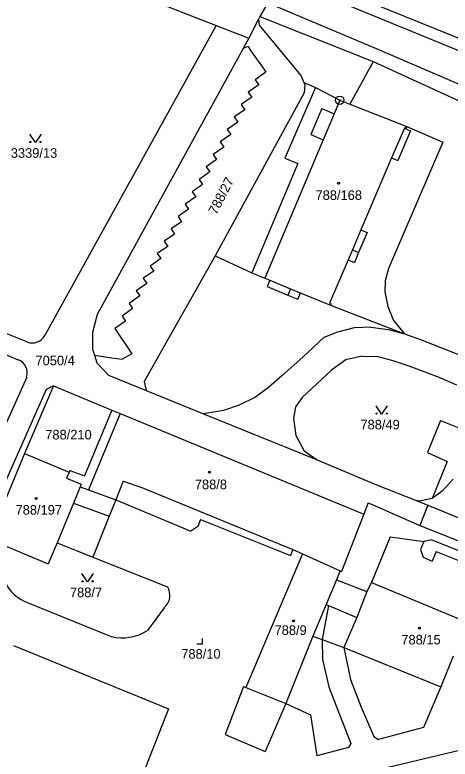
# Model space of a CAD drawing. Extents: x -593183 to -588034, y -1130415 to -1124994.
# Drawn here: x -592010.8 to -591933.7, y -1128398.9 to -1128267.2 of the extents above; entities that cross this region are included whole.
import ezdxf

# ---------------------------------------------------------------- set-up
doc = ezdxf.new("R2010")
doc.units = 0
for name, color, linetype in [('Vrstva 1', 7, 'Continuous'), ('Vrstva 18', 7, 'Continuous'), ('Vrstva 19', 7, 'Continuous'), ('Vrstva 24', 7, 'Continuous'), ('Vrstva 25', 7, 'Continuous'), ('Vrstva 4', 7, 'Continuous')]:
    doc.layers.add(name, color=color, linetype=linetype)

msp = doc.modelspace()

# ---------------------------------------------------------------- linework, layer by layer
at = {"layer": 'Vrstva 1'}
for p, q in [((-592007.9, -1128256.18), (-591975.11, -1128269.03)), ((-591960.97, -1128261.67), (-591931.65, -1128273.68)), ((-591955.86, -1128261.68), (-591814.3, -1128319.36)), ((-591965.98, -1128265.01), (-591967.38, -1128267.44)), ((-591965.98, -1128265.01), (-591946.82, -1128273.12)), ((-591967.63, -1128267.93), (-591969.35, -1128271.29)), ((-591967.38, -1128267.44), (-591967.63, -1128267.93)), ((-591967.38, -1128267.44), (-591947.92, -1128275.17)), ((-591975.11, -1128269.03), (-592005.34, -1128323.67)), ((-591975.11, -1128269.03), (-591969.35, -1128271.29)), ((-591969.35, -1128271.29), (-591970.34, -1128273.1)), ((-591970.34, -1128273.1), (-591996.22, -1128320.2)), ((-591946.82, -1128273.12), (-591931.29, -1128279.8)), ((-591947.54, -1128275.75), (-591951.51, -1128282.97)), ((-591947.92, -1128275.17), (-591947.36, -1128275.43)), ((-591947.36, -1128275.43), (-591947.54, -1128275.75)), ((-591947.36, -1128275.43), (-591931.88, -1128282.5)), ((-591959.64, -1128279.15), (-591957.58, -1128280.03)), ((-591959.64, -1128279.15), (-591959.45, -1128279.63)), ((-591959.45, -1128279.63), (-591959.58, -1128280.96)), ((-591957.58, -1128280.03), (-591953.27, -1128282.28)), ((-591959.58, -1128280.96), (-591975.29, -1128309.8)), ((-591953.27, -1128282.28), (-591951.51, -1128282.97)), ((-591951.51, -1128282.97), (-591941.4, -1128286.95)), ((-591941.4, -1128286.95), (-591935.02, -1128289.71)), ((-591935.02, -1128289.71), (-591944.66, -1128312.09)), ((-591975.29, -1128309.8), (-591968.82, -1128312.83)), ((-591968.82, -1128312.83), (-591966.52, -1128313.8)), ((-591944.66, -1128312.09), (-591945.21, -1128314.24)), ((-592036.9, -1128313.48), (-592008.84, -1128324.96)), ((-591966.52, -1128313.8), (-591965.64, -1128314.16)), ((-591965.64, -1128314.16), (-591966.1, -1128315.28)), ((-591945.21, -1128314.24), (-591945.29, -1128316.22)), ((-591966.1, -1128315.28), (-591962.43, -1128316.79)), ((-591962.43, -1128316.79), (-591960.71, -1128317.49)), ((-591960.26, -1128316.38), (-591960.71, -1128317.49)), ((-591960.26, -1128316.38), (-591954.92, -1128318.58)), ((-591945.29, -1128316.22), (-591944.75, -1128318.8)), ((-592031.02, -1128319.7), (-592010.18, -1128328.23)), ((-591954.92, -1128318.58), (-591941.8, -1128323.63)), ((-591944.75, -1128318.8), (-591943.78, -1128321.25)), ((-591996.22, -1128320.2), (-591997, -1128323.38)), ((-591947.77, -1128322.44), (-591950.73, -1128322.57)), ((-591947.77, -1128322.44), (-591944.62, -1128322.89)), ((-591943.78, -1128321.25), (-591941.8, -1128323.63)), ((-591997, -1128323.38), (-591997.01, -1128326.38)), ((-591953.68, -1128323.36), (-591956.07, -1128324.28)), ((-591950.73, -1128322.57), (-591953.68, -1128323.36)), ((-591944.62, -1128322.89), (-591941.8, -1128323.63)), ((-591941.8, -1128323.63), (-591938.97, -1128324.65)), ((-591956.07, -1128324.28), (-591959.73, -1128327.7)), ((-591938.97, -1128324.65), (-591927.04, -1128329.4)), ((-591997.01, -1128326.38), (-591996.69, -1128327.42)), ((-591996.69, -1128327.42), (-591996.27, -1128328.78)), ((-591959.73, -1128327.7), (-591963.53, -1128331.07)), ((-591949.27, -1128327.62), (-591952.17, -1128328.24)), ((-591949.27, -1128327.62), (-591946.54, -1128327.67)), ((-591946.54, -1128327.67), (-591943.88, -1128328.34)), ((-591996.27, -1128328.78), (-591994.2, -1128330.95)), ((-591952.17, -1128328.24), (-591954.7, -1128330.07)), ((-591943.88, -1128328.34), (-591941.05, -1128329.33)), ((-591954.7, -1128330.07), (-591959.92, -1128334.92)), ((-591941.05, -1128329.33), (-591938.19, -1128330.39)), ((-591938.19, -1128330.39), (-591935.41, -1128331.44)), ((-592008.67, -1128331.34), (-592017.33, -1128350.6)), ((-591994.2, -1128330.95), (-591987.53, -1128333.69)), ((-591963.53, -1128331.07), (-591965.89, -1128333.13)), ((-591935.41, -1128331.44), (-591932.59, -1128332.65)), ((-592003.92, -1128332.84), (-592009.05, -1128344.85)), ((-592003.92, -1128332.84), (-591993.62, -1128337.17)), ((-591987.53, -1128333.69), (-591977.4, -1128337.79)), ((-591965.89, -1128333.13), (-591968.2, -1128334.84)), ((-591968.2, -1128334.84), (-591971.05, -1128336.27)), ((-591959.92, -1128334.92), (-591961.07, -1128336.55)), ((-591971.05, -1128336.27), (-591973.81, -1128337.2)), ((-591961.07, -1128336.55), (-591961.43, -1128338.62)), ((-591993.62, -1128337.17), (-591998.41, -1128348.78)), ((-591993.62, -1128337.17), (-591992.12, -1128337.75)), ((-591992.12, -1128337.75), (-591949, -1128355.55)), ((-591973.81, -1128337.2), (-591977.4, -1128337.79)), ((-591977.4, -1128337.79), (-591957.29, -1128345.98)), ((-591961.43, -1128338.62), (-591961.04, -1128341.65)), ((-591961.04, -1128341.65), (-591959.55, -1128344.36)), ((-592009.05, -1128344.85), (-592013.81, -1128356.28)), ((-592009.05, -1128344.85), (-592001.18, -1128348.13)), ((-591959.55, -1128344.36), (-591957.29, -1128345.98)), ((-591957.29, -1128345.98), (-591946.79, -1128350.38)), ((-592001.18, -1128348.13), (-592001.62, -1128349.19)), ((-592001.02, -1128347.83), (-592001.18, -1128348.13)), ((-592001.02, -1128347.83), (-591998.41, -1128348.78)), ((-592001.62, -1128349.19), (-591999.03, -1128350.27)), ((-591933.18, -1128349.35), (-591935.12, -1128351.5)), ((-591999.2, -1128350.73), (-592000.38, -1128353.6)), ((-591999.03, -1128350.27), (-591999.2, -1128350.73)), ((-591946.79, -1128350.38), (-591939.87, -1128353.08)), ((-591935.12, -1128351.5), (-591936.93, -1128352.77)), ((-591936.93, -1128352.77), (-591938.85, -1128353.23)), ((-592000.38, -1128353.6), (-592003.29, -1128360.66)), ((-591992.91, -1128353.01), (-591994.09, -1128355.94)), ((-591992.91, -1128353.01), (-591979.64, -1128358.61)), ((-591948.22, -1128353.54), (-591949, -1128355.55)), ((-591948.22, -1128353.54), (-591947.55, -1128353.84)), ((-591947.55, -1128353.84), (-591939.08, -1128357.55)), ((-591939.87, -1128353.08), (-591937.65, -1128353.99)), ((-591939.87, -1128353.08), (-591938.85, -1128353.23)), ((-591937.65, -1128353.99), (-591939.08, -1128357.55)), ((-591937.65, -1128353.99), (-591900.44, -1128369.15)), ((-591994.09, -1128355.94), (-591996.96, -1128363.21)), ((-591977.89, -1128356.49), (-591978.4, -1128357.75)), ((-591977.89, -1128356.49), (-591962, -1128362.91)), ((-591949, -1128355.55), (-591952.93, -1128365.72)), ((-591978.4, -1128357.75), (-591979.64, -1128358.61)), ((-591939.08, -1128357.55), (-591915.81, -1128366.85)), ((-592003.29, -1128360.66), (-592004.84, -1128364.38)), ((-592003.29, -1128360.66), (-591996.96, -1128363.21)), ((-591944.35, -1128359.61), (-591947.64, -1128367.69)), ((-591944.35, -1128359.61), (-591938.4, -1128360.4)), ((-591938.4, -1128360.4), (-591938.98, -1128361.8)), ((-592012.2, -1128361.31), (-592004.84, -1128364.38)), ((-591961.57, -1128361.84), (-591962, -1128362.91)), ((-591961.57, -1128361.84), (-591959.84, -1128362.59)), ((-591938.98, -1128361.8), (-591938.53, -1128363.17)), ((-591996.96, -1128363.21), (-591983.73, -1128368.41)), ((-591959.84, -1128362.59), (-591969.88, -1128386.26)), ((-591959.84, -1128362.59), (-591953.21, -1128365.61)), ((-591938.53, -1128363.17), (-591936.89, -1128363.91)), ((-591936.21, -1128362.18), (-591936.89, -1128363.91)), ((-591936.21, -1128362.18), (-591917.66, -1128369.72)), ((-591953.21, -1128365.61), (-591953.86, -1128367.18)), ((-591953.21, -1128365.61), (-591952.93, -1128365.72)), ((-591953.86, -1128367.18), (-591955.67, -1128371.55)), ((-591953.86, -1128367.18), (-591948.49, -1128369.28)), ((-591947.64, -1128367.69), (-591948.49, -1128369.28)), ((-591947.64, -1128367.69), (-591900.03, -1128387.39)), ((-592008.99, -1128371.05), (-591993.69, -1128377.24)), ((-591984.33, -1128372.13), (-591987.3, -1128376.19)), ((-591955.67, -1128371.55), (-591958.01, -1128377.18)), ((-591955.67, -1128371.55), (-591955.26, -1128371.72)), ((-591955.26, -1128371.72), (-591950.25, -1128373.87)), ((-591950.25, -1128373.87), (-591952.53, -1128379.19)), ((-591958.01, -1128377.18), (-591962.82, -1128389.12)), ((-592010.99, -1128378.83), (-591983.57, -1128390.02)), ((-591952.53, -1128379.19), (-591935.39, -1128386.13)), ((-591933.2, -1128380.71), (-591935.39, -1128386.13)), ((-591970.3, -1128386.08), (-591973.56, -1128394.57)), ((-591970.3, -1128386.08), (-591969.88, -1128386.26)), ((-591962.82, -1128389.12), (-591966.47, -1128397.6)), ((-591983.57, -1128390.02), (-591993.46, -1128415.16)), ((-591973.56, -1128394.57), (-591966.47, -1128397.6)), ((-591929.86, -1128396.89), (-591949.87, -1128401.69))]:
    msp.add_line(p, q, dxfattribs=at)
for centre, radius, start, end in [((-592007.68, -1128322.7), 2.54, 242.9083, 337.5565), ((-592011.03, -1128330.56), 2.48, 341.7929, 70.0031), ((-592006.19, -1128364.65), 6.98, 196.4569, 246.3905), ((-591986.24, -1128369.91), 2.92, 310.7064, 30.9689), ((-591991.73, -1128369.18), 8.29, 256.3453, 302.3175)]:
    msp.add_arc(centre, radius, start, end, dxfattribs=at)
at = {"layer": 'Vrstva 24'}
for radius in [0.75, 0.0903]:
    msp.add_circle((-591953.27, -1128282.28), radius, dxfattribs=at)
at = {"layer": 'Vrstva 25'}
for q in [(-591977.57, -1128377.61), (-591978.57, -1128378.61)]:
    msp.add_line((-591977.57, -1128378.61), q, dxfattribs=at)
for points in [[(-592006.13, -1128288.27), (-592007.13, -1128289.77), (-592008.13, -1128288.27)], [(-591944.85, -1128336.36), (-591945.85, -1128337.86), (-591946.85, -1128336.36)], [(-591996.9, -1128366.07), (-591997.9, -1128367.57), (-591998.9, -1128366.07)]]:
    msp.add_lwpolyline(points, dxfattribs=at)
for centre, radius in [((-592008.03, -1128289.67), 0.1), ((-592006.23, -1128289.67), 0.1), ((-591953.46, -1128296.96), 0.175), ((-591953.46, -1128296.96), 0.15), ((-591946.75, -1128337.76), 0.1), ((-591944.95, -1128337.76), 0.1), ((-591976.31, -1128348.13), 0.175), ((-591976.31, -1128348.13), 0.15), ((-592007, -1128352.81), 0.175), ((-592007, -1128352.81), 0.15), ((-591998.8, -1128367.47), 0.1), ((-591997, -1128367.47), 0.1), ((-591961.47, -1128374.48), 0.175), ((-591961.47, -1128374.48), 0.15), ((-591939.15, -1128375.77), 0.175), ((-591939.15, -1128375.77), 0.15)]:
    msp.add_circle(centre, radius, dxfattribs=at)
at = {"layer": 'Vrstva 4'}
for p, q in [((-591967.63, -1128267.93), (-591967.55, -1128269)), ((-591967.55, -1128269), (-591960.14, -1128277.92)), ((-591969.5, -1128272.78), (-591970.34, -1128273.1)), ((-591969.5, -1128272.78), (-591969.06, -1128273.45)), ((-591969.06, -1128273.45), (-591966.96, -1128276.42)), ((-591966.33, -1128277.32), (-591968.24, -1128278.69)), ((-591966.96, -1128276.42), (-591966.33, -1128277.32)), ((-591968.24, -1128278.69), (-591967.6, -1128279.58)), ((-591960.14, -1128277.92), (-591959.64, -1128279.15)), ((-591967.6, -1128279.58), (-591969.45, -1128280.83)), ((-591957.58, -1128280.03), (-591962.99, -1128292.51)), ((-591969.45, -1128280.83), (-591968.83, -1128281.74)), ((-591968.83, -1128281.74), (-591970.7, -1128283.06)), ((-591953.27, -1128282.28), (-591954.28, -1128284.68)), ((-591970.07, -1128283.96), (-591971.93, -1128285.24)), ((-591970.7, -1128283.06), (-591970.07, -1128283.96)), ((-591956.44, -1128283.77), (-591958.38, -1128288.37)), ((-591956.44, -1128283.77), (-591954.28, -1128284.68)), ((-591971.93, -1128285.24), (-591971.31, -1128286.15)), ((-591954.28, -1128284.68), (-591956.21, -1128289.28)), ((-591971.31, -1128286.15), (-591973.19, -1128287.47)), ((-591973.19, -1128287.47), (-591972.56, -1128288.37)), ((-591941.82, -1128287.23), (-591944.08, -1128292.5)), ((-591940.72, -1128287.7), (-591942.97, -1128292.97)), ((-591941.77, -1128287.1), (-591941.82, -1128287.23)), ((-591941.82, -1128287.23), (-591940.72, -1128287.7)), ((-591941.77, -1128287.1), (-591941.51, -1128287.21)), ((-591941.4, -1128286.95), (-591941.51, -1128287.21)), ((-591972.56, -1128288.37), (-591974.42, -1128289.65)), ((-591956.21, -1128289.28), (-591966.52, -1128313.8)), ((-591958.38, -1128288.37), (-591956.21, -1128289.28)), ((-591973.8, -1128290.56), (-591975.68, -1128291.88)), ((-591974.42, -1128289.65), (-591973.8, -1128290.56)), ((-591975.68, -1128291.88), (-591975.05, -1128292.78)), ((-591975.05, -1128292.78), (-591976.91, -1128294.07)), ((-591960.69, -1128293.48), (-591968.82, -1128312.83)), ((-591962.99, -1128292.51), (-591960.69, -1128293.48)), ((-591944.08, -1128292.5), (-591949.53, -1128305.24)), ((-591944.08, -1128292.5), (-591942.97, -1128292.97)), ((-591976.91, -1128294.07), (-591976.28, -1128294.97)), ((-591976.28, -1128294.97), (-591978.16, -1128296.29)), ((-591977.53, -1128297.19), (-591979.39, -1128298.48)), ((-591978.16, -1128296.29), (-591977.53, -1128297.19)), ((-591979.39, -1128298.48), (-591978.76, -1128299.38)), ((-591978.76, -1128299.38), (-591980.63, -1128300.66)), ((-591980.63, -1128300.66), (-591980.01, -1128301.57)), ((-591980.01, -1128301.57), (-591981.88, -1128302.89)), ((-591981.25, -1128303.79), (-591983.11, -1128305.07)), ((-591981.88, -1128302.89), (-591981.25, -1128303.79)), ((-591983.11, -1128305.07), (-591982.49, -1128305.98)), ((-591949.53, -1128305.24), (-591951.03, -1128308.76)), ((-591949.53, -1128305.24), (-591948.42, -1128305.72)), ((-591982.49, -1128305.98), (-591984.34, -1128307.26)), ((-591948.42, -1128305.72), (-591949.92, -1128309.23)), ((-591984.34, -1128307.26), (-591983.71, -1128308.16)), ((-591983.71, -1128308.16), (-591985.55, -1128309.4)), ((-591951.03, -1128308.76), (-591951.78, -1128310.52)), ((-591951.03, -1128308.76), (-591949.92, -1128309.23)), ((-591949.92, -1128309.23), (-591950.67, -1128310.99)), ((-591975.29, -1128309.8), (-591987.86, -1128332.06)), ((-591984.94, -1128310.31), (-591986.81, -1128311.63)), ((-591985.55, -1128309.4), (-591984.94, -1128310.31)), ((-591951.78, -1128310.52), (-591955.06, -1128318.19)), ((-591951.78, -1128310.52), (-591950.67, -1128310.99)), ((-591986.81, -1128311.63), (-591986.18, -1128312.53)), ((-591986.18, -1128312.53), (-591988.04, -1128313.81)), ((-591988.04, -1128313.81), (-591987.42, -1128314.72)), ((-591965.64, -1128314.16), (-591961.97, -1128315.67)), ((-591987.42, -1128314.72), (-591989.29, -1128316.04)), ((-591961.97, -1128315.67), (-591962.43, -1128316.79)), ((-591961.97, -1128315.67), (-591960.26, -1128316.38)), ((-591988.66, -1128316.94), (-591990.55, -1128318.26)), ((-591989.29, -1128316.04), (-591988.66, -1128316.94)), ((-591990.55, -1128318.26), (-591989.92, -1128319.16)), ((-591955.06, -1128318.19), (-591954.8, -1128318.3)), ((-591954.8, -1128318.3), (-591954.92, -1128318.58)), ((-591989.92, -1128319.16), (-591991.8, -1128320.49)), ((-591991.8, -1128320.49), (-591991.16, -1128321.39)), ((-591991.16, -1128321.39), (-591993.06, -1128322.72)), ((-591993.06, -1128322.72), (-591990.05, -1128327.16)), ((-591996.69, -1128327.42), (-591993.26, -1128327.93)), ((-591990.05, -1128327.16), (-591991.79, -1128328.11)), ((-591993.26, -1128327.93), (-591991.79, -1128328.11)), ((-592003.92, -1128332.84), (-592005.24, -1128333.49)), ((-591987.86, -1128332.06), (-591987.53, -1128333.69)), ((-592005.24, -1128333.49), (-592015.1, -1128355.75)), ((-591992.12, -1128337.75), (-591997.72, -1128351.27)), ((-591935.43, -1128339.01), (-591937.74, -1128344.66)), ((-591935.43, -1128339.01), (-591931.89, -1128340.39)), ((-591937.74, -1128344.66), (-591934.27, -1128346.23)), ((-591934.27, -1128346.23), (-591936.93, -1128352.77)), ((-591991.57, -1128349.71), (-591992.91, -1128353.01)), ((-591991.57, -1128349.71), (-591988.28, -1128350.84)), ((-591999.2, -1128350.73), (-591997.72, -1128351.27)), ((-591997.72, -1128351.27), (-591992.91, -1128353.01)), ((-591988.28, -1128350.84), (-591961.57, -1128361.84)), ((-592000.38, -1128353.6), (-591994.09, -1128355.94)), ((-591936.98, -1128360.14), (-591938.4, -1128360.4)), ((-591936.98, -1128360.14), (-591916.47, -1128368.32)), ((-591948.49, -1128369.28), (-591950.25, -1128373.87)), ((-591955.26, -1128371.72), (-591956.4, -1128377.77)), ((-591958.01, -1128377.18), (-591956.4, -1128377.77)), ((-591956.4, -1128377.77), (-591952.53, -1128379.19)), ((-591956.4, -1128377.77), (-591956.31, -1128381.3)), ((-591952.53, -1128379.19), (-591951.35, -1128384.85)), ((-591956.31, -1128381.3), (-591955.2, -1128386.15)), ((-591951.35, -1128384.85), (-591949.5, -1128389.77)), ((-591969.88, -1128386.26), (-591962.82, -1128389.12)), ((-591955.2, -1128386.15), (-591953.33, -1128391.06)), ((-591935.39, -1128386.13), (-591938.44, -1128393.35)), ((-591962.82, -1128389.12), (-591958.45, -1128391.11)), ((-591949.5, -1128389.77), (-591947.21, -1128394.95)), ((-591958.45, -1128391.11), (-591957.33, -1128398.34)), ((-591953.33, -1128391.06), (-591951.28, -1128396.16)), ((-591938.44, -1128393.35), (-591946.4, -1128395.5)), ((-591947.21, -1128394.95), (-591946.4, -1128395.5)), ((-591951.28, -1128396.16), (-591951.71, -1128396.9)), ((-591951.71, -1128396.9), (-591957.33, -1128398.34))]:
    msp.add_line(p, q, dxfattribs=at)

# ---------------------------------------------------------------- texts
at = {"layer": 'Vrstva 18'}
for s, p in [('3339/13', (-592011.48, -1128292.47)), ('7050/4', (-592007.11, -1128329.21)), ('788/49', (-591949.6, -1128340.56)), ('788/210', (-592005.38, -1128342.34)), ('788/7', (-592001.01, -1128370.27))]:
    msp.add_text(s, height=1.7, dxfattribs=at).set_placement(p)
msp.add_text('788/27', height=1.7, rotation=62.8577, dxfattribs=at).set_placement((-591975.09, -1128302.67))
at = {"layer": 'Vrstva 19'}
for s, p in [('788/168', (-591957.55, -1128299.93)), ('788/8', (-591978.91, -1128351.15)), ('788/197', (-592010.64, -1128355.66)), ('788/9', (-591964.8, -1128376.96)), ('788/15', (-591942.36, -1128378.64)), ('788/10', (-591981.31, -1128381.16))]:
    msp.add_text(s, height=1.7, dxfattribs=at).set_placement(p)

doc.saveas('drawing.dxf')
